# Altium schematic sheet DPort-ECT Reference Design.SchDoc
size A4; CheckedBy: AIoT事业部; Author: 工控机; DocumentNumber: 1; SheetNumber: 1; SheetTotal: 1; PageSetup: Record=PageOptions¦CenterHorizontal=True¦CenterVertical=True¦PrintScale=1.00¦XCorrection=1.00¦YCorrection=1.00¦PrintKind=0¦BorderSize=5000000¦LeftOffset=0¦BottomOffset=0¦Orientation=2¦PaperLength=1000¦PaperWidth=1000¦Scale=100¦PaperSource=7¦PrintQuality=600¦MediaType=1¦DitherType=10¦PaperKind=A4¦PrintScaleMode=1; DesignDate: 2023-12-19; CheckDate: 2023-12-22; SheetName: DPort-ECT 参考设计电路; SheetVersion: Rev.A; SheetDescription: DPort-ECT 参考设计电路; ProductName: 集成式EtherCAT从站模块; ProductModel: DPort-ECT
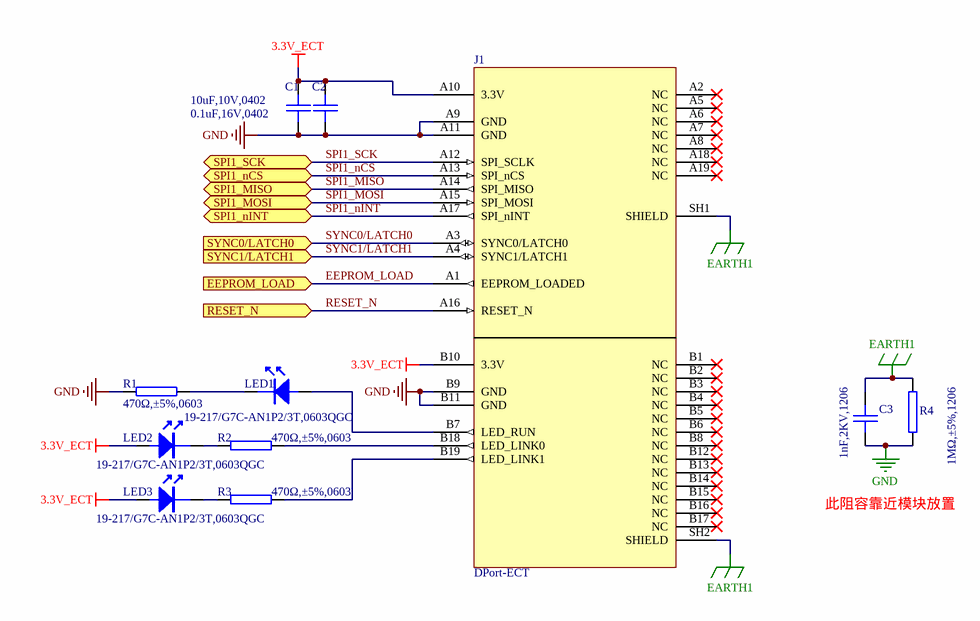
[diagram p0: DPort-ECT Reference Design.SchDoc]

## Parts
C1  10uF,10V,0402  [0402C]
C2  0.1uF,16V,0402  [0402C]
C3  1nF,2KV,1206  [1206C]
J1  DPort-ECT  [DPort]
LED1  19-217/G7C-AN1P2/3T,0603QGC  [LED-0603]
LED2  19-217/G7C-AN1P2/3T,0603QGC  [LED-0603]
LED3  19-217/G7C-AN1P2/3T,0603QGC  [LED-0603]
R1  470Ω,±5%,0603  [0603R]
R2  470Ω,±5%,0603  [0603R]
R3  470Ω,±5%,0603  [0603R]
R4  1MΩ,±5%,1206  [1206R]

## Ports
EEPROM_LOAD (in), RESET_N (in), SPI1_MISO (bidir), SPI1_MOSI (bidir), SPI1_nCS (bidir), SPI1_nINT (bidir), SPI1_SCK (bidir), SYNC0/LATCH0 (in), SYNC1/LATCH1 (in)

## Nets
3.3V_ECT: C1.1 C2.1 J1.A10(3.3V) J1.B10(3.3V) LED2.1 LED3.1
EARTH1: C3.2 J1.SH1(SHIELD) J1.SH2(SHIELD) R4.2
GND: C1.2 C2.2 C3.1 J1.A9(GND) J1.A11(GND) J1.B9(GND) J1.B11(GND) R1.1 R4.1
EEPROM_LOAD: J1.A1(EEPROM_LOADED) ; port EEPROM_LOAD
RESET_N: J1.A16(RESET_N) ; port RESET_N
SPI1_MISO: J1.A14(SPI_MISO) ; port SPI1_MISO
SPI1_MOSI: J1.A15(SPI_MOSI) ; port SPI1_MOSI
SPI1_nCS: J1.A13(SPI_nCS) ; port SPI1_nCS
SPI1_nINT: J1.A17(SPI_nINT) ; port SPI1_nINT
SPI1_SCK: J1.A12(SPI_SCLK) ; port SPI1_SCK
SYNC0/LATCH0: J1.A3(SYNC0/LATCH0) ; port SYNC0/LATCH0
SYNC1/LATCH1: J1.A4(SYNC1/LATCH1) ; port SYNC1/LATCH1
NetJ1_B7: J1.B7(LED_RUN) LED1.1
NetJ1_B18: J1.B18(LED_LINK0) R2.2
NetJ1_B19: J1.B19(LED_LINK1) R3.2
NetLED1_2: LED1.2 R1.2
NetLED2_2: LED2.2 R2.1
NetLED3_2: LED3.2 R3.1

Not connected (* = marked no-connect by the designer): J1 A2(NC)* A5(NC)* A6(NC)* A7(NC)* A8(NC)* A18(NC)* A19(NC)* B1(NC)* B2(NC)* B3(NC)* B4(NC)* B5(NC)* B6(NC)* B8(NC)* B12(NC)* B13(NC)* B14(NC)* B15(NC)* B16(NC)* B17(NC)*

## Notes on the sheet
- 此阻容靠近模块放置

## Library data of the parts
C1 = 02.01.00527: GRM155R61A106ME11D,0402,muRata,10uF,X5R,±20%,10V; 名称: 电容; 封装: 0402; 贴片和直插: SMT; 环保状态: RoHS2.0; PCB备注: 200927ZW; 器件优选方案: 通用物料; 生产单位: PCS
C2 = 02.01.00513: CC0402KRX7R7BB104,0402,YAGEO,0.1uF,X7R,±10%,16V,; 名称: 电容; 封装: 0402; 贴片和直插: SMT; 环保状态: RoHS2.0; PCB备注: 211228yyj; 器件优选方案: 通用物料; 生产单位: PCS
C3 = 02.01.00212: CC1206KKX7RDBB102,1206,YAGEO,1nF,X7R,±10%,2KV,; 名称: 电容; 封装: 1206; 贴片和直插: SMT; 旧物料代码: 1.02.03.0003; 器件优选方案: 不推荐使用
J1 = DPort-ECT-Pro: 集成式EtherCAT从站
LED1-LED3 = 04.04.00003: 19-217/G7C-AN1P2/3T,0603QGC,SMD,BRIGHT,绿色,; 旧物料代码: 1.04.05.0009; 名称: 发光二极管; 封装: 0603; 贴片和直插: SMT; 环保状态: RoHS2.0; 器件优选方案: 通用物料; 生产单位: PCS
R1-R3 = 01.01.00048: RTT03471JTP,0603,RALEC,470Ω,±5%,1/10W,; 旧物料代码: 1.01.01.0032; 名称: 电阻; 封装: 0603; 厂商: BTW00003; 贴片和直插: SMT; 环保状态: RoHS2.0+REACH; 器件优选方案: 可用; 生产单位: PCS
R4 = 01.01.00041: RTT06105JTP,1206,RALEC,1MΩ,±5%,1/4W,; 名称: 电阻; 封装: 1206; 贴片和直插: SMT; 旧物料代码: 1.01.03.0019; 器件优选方案: 通用物料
